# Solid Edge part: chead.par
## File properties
Title: Cross Head
Subject: Carrier Assembly
Author: edge
Keywords: Block
Comments: Cross Head
Template: metric.par
Last saved by: edge
Revision: 35
Application: Solid Edge
File Size: 0
Number of Sheets: 0
Number of Objects: 0
Username: edge
文書内容のタイプ: 0
Material: Steel
Face Style: Steel
Fill Style: ANSI32(Steel)
Virtual Style: Machined steel
Coef. of Thermal Exp: 1.3e-05
Thermal Conductivity: 32.0
Specific Heat: 481.0
Modulus of Elasticity: 199947953000.0
Poisson's Ratio: 0.29
Yield Stress: 262000766.0
Ultimate Stress: 358527364.0
Elongation: 0.0
Category: Machined Block
Manager: Brian Little
Company: Wheels R Us
Density: 7702
Accuracy: 0.00
Document Number: C-3701
Revision: 1
Project Name: Trolley Wheel Assembly
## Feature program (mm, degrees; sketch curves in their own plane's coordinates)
sketch for "unnamed Protrusion 1" plane through (0, 0, 0) normal (0, -1, 0) x-axis (1, 0, 0)
  line (-53.3125, 21.0114) -> (66.6875, 21.0114)
  line (66.6875, 21.0114) -> (66.6875, -28.9886)
  line (66.6875, -28.9886) -> (-53.3125, -28.9886)
  line (-53.3125, -28.9886) -> (-53.3125, 21.0114)
extrude "unnamed Protrusion 1" add finite 140 along -normal
sketch for "unnamed Hole 1" plane through (6.6875, 0, -3.9886) normal (0, -1, 0) x-axis (1, 0, 0)
  hole centre (30, 0) bore radius 10
hole "unnamed Hole 1" through
sketch for "Hole_2" plane through (6.6875, 0, -3.9886) normal (0, -1, 0) x-axis (1, 0, 0)
  hole centre (-30, 0) bore radius 10
hole "Hole_2" through
pattern "unnamed Pattern 1" of "unnamed Hole 1", "Hole_2"
sketch for "Hole_3" plane through (6.6875, 70, 21.0114) normal (0, 0, 1) x-axis (1, 0, 0)
  hole centre (0, 0) bore radius 10
hole "Hole_3" through  CounterBoreDepth = 12 mm
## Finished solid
Body 1: solid body, 11 faces, 20 edges, 8 vertices.
  Faces by surface: plane 7, cylinder 4
  Edges by curve: line 12, circle 8
Bounding box of the edges (mm): 120.000 x 140.000 x 50.000, from (-53.3125, 0, -28.9886) to (66.6875, 140, 21.0114).
Cylindrical faces by radius (mm): R10 x3, R18 x1
Planar faces by outward normal: +x 1, +y 1, +z 2, -x 1, -y 1, -z 1
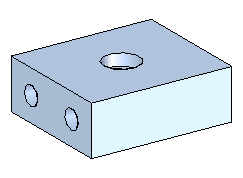
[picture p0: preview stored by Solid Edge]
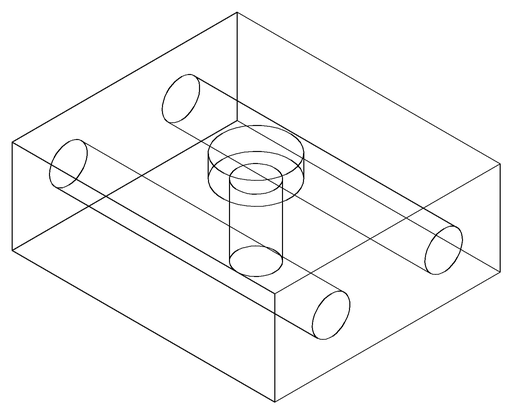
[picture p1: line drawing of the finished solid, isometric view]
